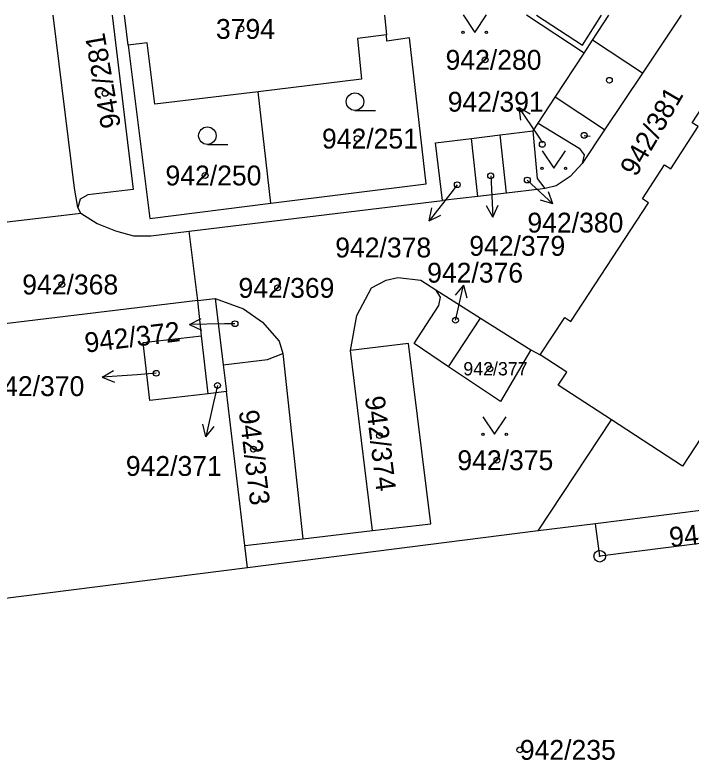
# Model space of a CAD drawing. Extents: x -640141 to -639316, y -1044695 to -1044469.
# Drawn here: x -639423.2 to -639365.3, y -1044535.2 to -1044471.3 of the extents above; entities that cross this region are included whole.
import ezdxf

# ---------------------------------------------------------------- set-up
doc = ezdxf.new("R2010")
doc.units = 0
for name, color, linetype in [('Default', 7, 'Continuous'), ('Definiční body', 7, 'Continuous'), ('Hranice parcel', 7, 'Continuous'), ('Parcelní čísla', 7, 'Continuous'), ('Pop  PČ popisy', 7, 'Continuous'), ('Značky bodu BP', 7, 'Continuous'), ('Značky kultur', 7, 'Continuous')]:
    doc.layers.add(name, color=color, linetype=linetype)

# ---------------------------------------------------------------- blocks, each defined once
blk = doc.blocks.new('1029380')
at = {"layer": 'Pop  PČ popisy'}
for p, q in [((0.675, 2.924), (-0.038, 2.061)), ((0, 0), (0.675, 2.924)), ((0.675, 2.924), (0.938, 1.836))]:
    blk.add_line(p, q, dxfattribs=at)
blk = doc.blocks.new('1029390')
at = {"layer": 'Pop  PČ popisy'}
for p, q in [((-3.001, -0.052), (-2.008, 0.466)), ((0, 0), (-3.001, -0.052)), ((-3.001, -0.052), (-1.99, -0.536))]:
    blk.add_line(p, q, dxfattribs=at)
blk = doc.blocks.new('1029391')
at = {"layer": 'Pop  PČ popisy'}
for p, q in [((0, 0), (-1.848, -2.365)), ((-1.848, -2.365), (-1.626, -1.267)), ((-1.848, -2.365), (-0.836, -1.884))]:
    blk.add_line(p, q, dxfattribs=at)
blk = doc.blocks.new('1029393')
at = {"layer": 'Pop  PČ popisy'}
for p, q in [((0, 0), (0.157, -2.997)), ((0.157, -2.997), (-0.395, -2.023)), ((0.157, -2.997), (0.605, -1.971))]:
    blk.add_line(p, q, dxfattribs=at)
blk = doc.blocks.new('1029394')
at = {"layer": 'Pop  PČ popisy'}
for p, q in [((0, 0), (2.195, -2.047)), ((2.195, -2.047), (1.804, -0.997)), ((2.195, -2.047), (1.121, -1.73))]:
    blk.add_line(p, q, dxfattribs=at)
blk = doc.blocks.new('1029396')
at = {"layer": 'Pop  PČ popisy'}
for p, q in [((0, 0), (-1.678, 2.488)), ((-1.678, 2.488), (-0.703, 1.938)), ((-1.678, 2.488), (-1.533, 1.378))]:
    blk.add_line(p, q, dxfattribs=at)
blk = doc.blocks.new('1029398')
at = {"layer": 'Pop  PČ popisy'}
for p, q in [((-2.994, -0.209), (-2.03, 0.36)), ((0, 0), (-2.994, -0.209)), ((-2.994, -0.209), (-1.96, -0.639))]:
    blk.add_line(p, q, dxfattribs=at)
blk = doc.blocks.new('1029400')
at = {"layer": 'Pop  PČ popisy'}
for p, q in [((0, 0), (-0.675, -2.924)), ((-0.675, -2.924), (-0.938, -1.836)), ((-0.675, -2.924), (0.038, -2.061))]:
    blk.add_line(p, q, dxfattribs=at)
blk = doc.blocks.new('3.14121')
at = {"layer": 'Značky kultur'}
blk.add_lwpolyline([(-1, 1.501), (0, 0), (1, 1.501)], dxfattribs=at)
for centre in [(-1, 0.001), (1, 0.001)]:
    blk.add_circle(centre, 0.1, dxfattribs=at)
blk = doc.blocks.new('3.14122')
at = {"layer": 'Značky kultur'}
blk.add_lwpolyline([(-1, 1.501), (0, 0), (1, 1.501)], dxfattribs=at)
for centre in [(-1, 0.001), (1, 0.001)]:
    blk.add_circle(centre, 0.1, dxfattribs=at)
blk = doc.blocks.new('3.14127')
at = {"layer": 'Značky kultur'}
blk.add_lwpolyline([(-1, 1.501), (0, 0), (1, 1.501)], dxfattribs=at)
for centre in [(-1, 0.001), (1, 0.001)]:
    blk.add_circle(centre, 0.1, dxfattribs=at)
blk = doc.blocks.new('3.041250')
at = {"layer": 'Značky kultur'}
blk.add_line((0.007, 0), (1.757, 0), dxfattribs=at)
blk.add_circle((0.007, 0.75), 0.75, dxfattribs=at)
blk = doc.blocks.new('3.041251')
at = {"layer": 'Značky kultur'}
blk.add_line((0.007, 0), (1.757, 0), dxfattribs=at)
blk.add_circle((0.007, 0.75), 0.75, dxfattribs=at)
blk = doc.blocks.new('B_PRN10031')
at = {"layer": 'Definiční body'}
blk.add_circle((0, 0), 0.25, dxfattribs=at)
blk.add_circle((0, 0), 0.25, dxfattribs=at)
blk = doc.blocks.new('B_PRN10152')
at = {"layer": 'Definiční body'}
blk.add_circle((0, 0), 0.25, dxfattribs=at)
blk.add_circle((0, 0), 0.25, dxfattribs=at)
blk = doc.blocks.new('B_PRN10153')
at = {"layer": 'Definiční body'}
blk.add_circle((0, 0), 0.25, dxfattribs=at)
blk.add_circle((0, 0), 0.25, dxfattribs=at)
blk = doc.blocks.new('B_PRN10154')
at = {"layer": 'Definiční body'}
blk.add_circle((0, 0), 0.25, dxfattribs=at)
blk.add_circle((0, 0), 0.25, dxfattribs=at)
blk = doc.blocks.new('B_PRN10155')
at = {"layer": 'Definiční body'}
blk.add_circle((0, 0), 0.25, dxfattribs=at)
blk.add_circle((0, 0), 0.25, dxfattribs=at)
blk = doc.blocks.new('B_PRN10156')
at = {"layer": 'Definiční body'}
blk.add_circle((0, 0), 0.25, dxfattribs=at)
blk.add_circle((0, 0), 0.25, dxfattribs=at)
blk = doc.blocks.new('B_PRN10157')
at = {"layer": 'Definiční body'}
blk.add_circle((0, 0), 0.25, dxfattribs=at)
blk.add_circle((0, 0), 0.25, dxfattribs=at)
blk = doc.blocks.new('B_PRN10158')
at = {"layer": 'Definiční body'}
blk.add_circle((0, 0), 0.25, dxfattribs=at)
blk.add_circle((0, 0), 0.25, dxfattribs=at)
blk = doc.blocks.new('B_PRN10159')
at = {"layer": 'Definiční body'}
blk.add_circle((0, 0), 0.25, dxfattribs=at)
blk.add_circle((0, 0), 0.25, dxfattribs=at)
blk = doc.blocks.new('B_PRN10160')
at = {"layer": 'Definiční body'}
blk.add_circle((0, 0), 0.25, dxfattribs=at)
blk.add_circle((0, 0), 0.25, dxfattribs=at)
blk = doc.blocks.new('B_PRN10161')
at = {"layer": 'Definiční body'}
blk.add_circle((0, 0), 0.25, dxfattribs=at)
blk.add_circle((0, 0), 0.25, dxfattribs=at)
blk = doc.blocks.new('B_PRN10162')
at = {"layer": 'Definiční body'}
blk.add_circle((0, 0), 0.25, dxfattribs=at)
blk.add_circle((0, 0), 0.25, dxfattribs=at)
blk = doc.blocks.new('B_PRN10163')
at = {"layer": 'Definiční body'}
blk.add_circle((0, 0), 0.25, dxfattribs=at)
blk.add_circle((0, 0), 0.25, dxfattribs=at)
blk = doc.blocks.new('B_PRN10164')
at = {"layer": 'Definiční body'}
blk.add_circle((0, 0), 0.25, dxfattribs=at)
blk.add_circle((0, 0), 0.25, dxfattribs=at)
blk = doc.blocks.new('B_PRN10172')
at = {"layer": 'Definiční body'}
blk.add_circle((0, 0), 0.25, dxfattribs=at)
blk.add_circle((0, 0), 0.25, dxfattribs=at)
blk = doc.blocks.new('B_PRN10175')
at = {"layer": 'Definiční body'}
blk.add_circle((0, 0), 0.25, dxfattribs=at)
blk.add_circle((0, 0), 0.25, dxfattribs=at)
blk = doc.blocks.new('B_PRN10176')
at = {"layer": 'Definiční body'}
blk.add_circle((0, 0), 0.25, dxfattribs=at)
blk.add_circle((0, 0), 0.25, dxfattribs=at)
blk = doc.blocks.new('B_PRN10262')
at = {"layer": 'Definiční body'}
blk.add_circle((0, 0), 0.25, dxfattribs=at)
blk.add_circle((0, 0), 0.25, dxfattribs=at)
blk = doc.blocks.new('B_PRN10263')
at = {"layer": 'Definiční body'}
blk.add_circle((0, 0), 0.25, dxfattribs=at)
blk.add_circle((0, 0), 0.25, dxfattribs=at)
blk = doc.blocks.new('B_PRN10268')
at = {"layer": 'Definiční body'}
blk.add_circle((0, 0), 0.25, dxfattribs=at)
blk.add_circle((0, 0), 0.25, dxfattribs=at)
blk = doc.blocks.new('B_PRN10269')
at = {"layer": 'Definiční body'}
blk.add_circle((0, 0), 0.25, dxfattribs=at)
blk.add_circle((0, 0), 0.25, dxfattribs=at)
blk = doc.blocks.new('B_PRN10291')
at = {"layer": 'Definiční body'}
blk.add_circle((0, 0), 0.25, dxfattribs=at)
blk.add_circle((0, 0), 0.25, dxfattribs=at)
blk = doc.blocks.new('1.051007')
at = {"layer": 'Značky bodu BP'}
for radius in [0.5, 0.0303]:
    blk.add_circle((0, 0), radius, dxfattribs=at)

msp = doc.modelspace()

# ---------------------------------------------------------------- linework, layer by layer
at = {"layer": 'Hranice parcel'}
for p, q in [((-639413.49, -1044473.91), (-639413.799, -1044471.355)), ((-639366.116, -1044471.355), (-639369.43, -1044476.32)), ((-639374.42, -1044474.6), (-639373.7, -1044473.5)), ((-639369.43, -1044476.32), (-639373.7, -1044473.5)), ((-639376.9, -1044478.39), (-639374.42, -1044474.6)), ((-639369.43, -1044476.32), (-639372.67, -1044481.19)), ((-639401.27, -1044487.46), (-639402.34, -1044477.91)), ((-639378.35, -1044480.61), (-639376.9, -1044478.39)), ((-639372.67, -1044481.19), (-639376.9, -1044478.39)), ((-639378.78, -1044481.27), (-639378.35, -1044480.61)), ((-639381.63, -1044481.61), (-639378.78, -1044481.27)), ((-639372.67, -1044481.19), (-639374.59, -1044484.06)), ((-639384.08, -1044481.91), (-639381.63, -1044481.61)), ((-639383.54, -1044486.89), (-639384.08, -1044481.91)), ((-639381.07, -1044486.6), (-639381.63, -1044481.61)), ((-639381.07, -1044486.6), (-639383.54, -1044486.89)), ((-639408.25, -1044489.85), (-639386.56, -1044487.24)), ((-639383.54, -1044486.89), (-639386.56, -1044487.24)), ((-639417.54, -1044488.33), (-639417.8, -1044487.84)), ((-639407.5, -1044495.81), (-639408.25, -1044489.85)), ((-639387.13, -1044494.89), (-639383.29, -1044497.31)), ((-639407.5, -1044495.81), (-639406.03, -1044495.63)), ((-639407.2, -1044498.84), (-639407.5, -1044495.81)), ((-639406.03, -1044495.63), (-639405.35, -1044501.3)), ((-639386.04, -1044501.48), (-639383.29, -1044497.31)), ((-639383.29, -1044497.31), (-639378.99, -1044500.03)), ((-639406.64, -1044503.81), (-639407.2, -1044498.84)), ((-639378.99, -1044500.03), (-639378.18, -1044500.45)), ((-639400.23, -1044500.33), (-639398.52, -1044516.22)), ((-639392.56, -1044515.52), (-639394.44, -1044500.1)), ((-639405.35, -1044501.3), (-639405.07, -1044503.6)), ((-639405.07, -1044503.6), (-639406.64, -1044503.81)), ((-639403.48, -1044516.79), (-639405.07, -1044503.6)), ((-639378.36, -1044515.55), (-639372.09, -1044506.02)), ((-639373.44, -1044514.93), (-639378.36, -1044515.55)), ((-639373.09, -1044517.71), (-639373.44, -1044514.93)), ((-639378.36, -1044515.55), (-639403.25, -1044518.7)), ((-639398.52, -1044516.22), (-639392.56, -1044515.52)), ((-639403.48, -1044516.79), (-639398.52, -1044516.22)), ((-639403.25, -1044518.7), (-639403.48, -1044516.79)), ((-639403.25, -1044518.7), (-639441.11, -1044523.49))]:
    msp.add_line(p, q, dxfattribs=at)
for points in [[(-639417.8, -1044487.84), (-639418.08, -1044486.19), (-639419.911, -1044471.355)], [(-639414.843, -1044471.355), (-639413.06, -1044486.28), (-639416.93, -1044486.74), (-639417.58, -1044487.13), (-639417.8, -1044487.84)], [(-639391.537, -1044471.355), (-639391.34, -1044473.05)], [(-639374.42, -1044474.6), (-639379.355, -1044471.355)], [(-639378.491, -1044471.355), (-639374.57, -1044473.91), (-639372.924, -1044471.355)], [(-639378.18, -1044500.45), (-639376.09, -1044497.27), (-639375.57, -1044497.6), (-639368.91, -1044487.42), (-639369.42, -1044487.1), (-639367.53, -1044484.19), (-639367.01, -1044484.52), (-639364.66, -1044480.9), (-639365.18, -1044480.57), (-639363.29, -1044477.68), (-639362.77, -1044478.02), (-639358.433, -1044471.355)], [(-639373.7, -1044473.5), (-639372.299, -1044471.355)], [(-639391.34, -1044473.05), (-639393.85, -1044473.36), (-639393.48, -1044476.84), (-639402.34, -1044477.91)], [(-639401.27, -1044487.46), (-639387.96, -1044485.8), (-639389.39, -1044473.3), (-639391.32, -1044473.57), (-639391.34, -1044473.05)], [(-639402.34, -1044477.91), (-639411.19, -1044478.98), (-639411.84, -1044473.73), (-639413.49, -1044473.91)], [(-639413.49, -1044473.91), (-639411.61, -1044488.77), (-639401.27, -1044487.46)], [(-639378.35, -1044480.61), (-639374.85, -1044482.76), (-639374.41, -1044483.33), (-639374.59, -1044484.06)], [(-639377.76, -1044486.21), (-639378.42, -1044485.35), (-639378.78, -1044481.27)], [(-639386.56, -1044487.24), (-639387.16, -1044482.28), (-639384.08, -1044481.91)], [(-639374.59, -1044484.06), (-639375.61, -1044485.17), (-639376.83, -1044485.98), (-639377.76, -1044486.21)], [(-639377.76, -1044486.21), (-639378.18, -1044486.27), (-639381.07, -1044486.6)], [(-639424.88, -1044489.17), (-639424.59, -1044489.14), (-639417.54, -1044488.33)], [(-639417.54, -1044488.33), (-639416.13, -1044489.21), (-639414.56, -1044489.84), (-639413.02, -1044490.25), (-639411.55, -1044490.25), (-639408.25, -1044489.85)], [(-639394.44, -1044500.1), (-639393.9, -1044497.08), (-639392.65, -1044494.71), (-639391.37, -1044494.06), (-639390.38, -1044493.82), (-639388.4, -1044494.07), (-639387.13, -1044494.89)], [(-639386.04, -1044501.48), (-639388.98, -1044499.5), (-639386.87, -1044496.23), (-639386.74, -1044495.51), (-639387.13, -1044494.89)], [(-639407.5, -1044495.81), (-639425.72, -1044497.99), (-639428.82, -1044498.36)], [(-639406.03, -1044495.63), (-639403.61, -1044496.51), (-639401.96, -1044497.65), (-639400.54, -1044499.29), (-639400.23, -1044500.33)], [(-639406.64, -1044503.81), (-639411.61, -1044504.38), (-639412.19, -1044499.4), (-639407.2, -1044498.84)], [(-639392.56, -1044515.52), (-639387.56, -1044514.93), (-639389.46, -1044499.48), (-639394.44, -1044500.1)], [(-639378.99, -1044500.03), (-639381.6, -1044504.46), (-639386.04, -1044501.48)], [(-639405.35, -1044501.3), (-639401.55, -1044500.85), (-639400.23, -1044500.33)], [(-639372.09, -1044506.02), (-639376.65, -1044503.06), (-639375.9, -1044501.94), (-639378.18, -1044500.45)], [(-639358.42, -1044501.14), (-639360.53, -1044504.35), (-639361.78, -1044503.53), (-639365.99, -1044509.99), (-639372.09, -1044506.02)], [(-639343.37, -1044511.13), (-639346.39, -1044511.51), (-639373.44, -1044514.93)], [(-639342.29, -1044511.86), (-639352.5, -1044513.15), (-639352.26, -1044515.08), (-639373.09, -1044517.71)]]:
    msp.add_lwpolyline(points, dxfattribs=at)
at = {"layer": 'Pop  PČ popisy'}
for p, q in [((-639377.95, -1044482.3), (-639378.34, -1044481.73)), ((-639374.42, -1044481.65), (-639373.92, -1044481.71)), ((-639382.43, -1044485.12), (-639382.4, -1044485.66)), ((-639385.29, -1044485.88), (-639385.85, -1044486.6)), ((-639385.44, -1044497.49), (-639385.42, -1044497.4)), ((-639404.33, -1044497.79), (-639405.22, -1044497.8)), ((-639411.07, -1044502.04), (-639412.7, -1044502.17)), ((-639405.83, -1044503.08), (-639406.16, -1044504.55))]:
    msp.add_line(p, q, dxfattribs=at)

# ---------------------------------------------------------------- block references
at = {"layer": 'Default'}
for name, p in [('3.14127', (-639383.79, -1044472.83)), ('B_PRN10291', (-639403.82, -1044472.53)), ('B_PRN10262', (-639382.9, -1044475.18)), ('B_PRN10164', (-639372.26, -1044476.93)), ('B_PRN10263', (-639415.46, -1044478.05)), ('3.041251', (-639394.06, -1044479.51)), ('1029396', (-639378.34, -1044481.73)), ('3.041250', (-639406.7, -1044482.43)), ('B_PRN10163', (-639374.42, -1044481.65)), ('B_PRN10269', (-639393.85, -1044481.93)), ('B_PRN10172', (-639378.01, -1044482.42)), ('3.14122', (-639377.02, -1044484.47)), ('B_PRN10268', (-639406.89, -1044485.09)), ('B_PRN10161', (-639382.43, -1044485.12)), ('B_PRN10162', (-639379.29, -1044485.48)), ('B_PRN10160', (-639385.29, -1044485.88)), ('1029393', (-639382.4, -1044485.66)), ('1029394', (-639379.29, -1044485.48)), ('1029391', (-639385.85, -1044486.6)), ('B_PRN10152', (-639419.16, -1044494.43)), ('B_PRN10153', (-639400.68, -1044494.72)), ('1029380', (-639385.42, -1044497.4)), ('1029390', (-639405.22, -1044497.8)), ('B_PRN10158', (-639385.44, -1044497.49)), ('B_PRN10154', (-639404.33, -1044497.79)), ('1029398', (-639412.7, -1044502.17)), ('B_PRN10175', (-639411.07, -1044502.04)), ('B_PRN10159', (-639382.5, -1044501.65)), ('B_PRN10176', (-639405.83, -1044503.08)), ('1029400', (-639406.16, -1044504.55)), ('3.14121', (-639382.1, -1044507.26)), ('B_PRN10156', (-639391.95, -1044507.38)), ('B_PRN10155', (-639402.75, -1044508.54)), ('B_PRN10157', (-639381.89, -1044509.49)), ('1.051007', (-639373.09, -1044517.71)), ('B_PRN10031', (-639379.93, -1044534.31))]:
    msp.add_blockref(name, p, dxfattribs=at)

# ---------------------------------------------------------------- texts
at = {"layer": 'Parcelní čísla'}
for s, height, p in [('3794', 1.7, (-639405.963, -1044473.38)), ('942/280', 1.7, (-639386.293, -1044476.03)), ('942/391', 1.7, (-639386.108, -1044479.62)), ('942/251', 1.7, (-639396.878, -1044482.78)), ('942/250', 1.7, (-639410.283, -1044485.94)), ('942/380', 1.7, (-639379.283, -1044489.98)), ('942/378', 1.7, (-639395.743, -1044492.11)), ('942/379', 1.7, (-639384.262, -1044491.97)), ('942/376', 1.7, (-639387.872, -1044494.27)), ('942/368', 1.7, (-639422.553, -1044495.28)), ('942/369', 1.7, (-639404.032, -1044495.57)), ('942/377', 1.139, (-639384.773, -1044502.219)), ('942/370', 1.7, (-639425.453, -1044503.99)), ('942/375', 1.7, (-639385.283, -1044510.34)), ('942/371', 1.7, (-639413.678, -1044510.83)), ('942/235', 1.7, (-639379.93, -1044535.16))]:
    msp.add_text(s, height=height, dxfattribs=at).set_placement(p)
for s, rotation, p in [('942/281', 100, (-639414.097, -1044480.885)), ('942/381', 60, (-639369.977, -1044485.277)), ('942/372', 7, (-639417.103, -1044500.277)), ('942/374', 277, (-639393.212, -1044504.076)), ('942/373', 277, (-639404.007, -1044505.276)), ('942/249', 6, (-639367.045, -1044516.945))]:
    msp.add_text(s, height=1.7, rotation=rotation, dxfattribs=at).set_placement(p)

doc.saveas('drawing.dxf')
